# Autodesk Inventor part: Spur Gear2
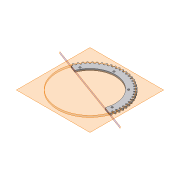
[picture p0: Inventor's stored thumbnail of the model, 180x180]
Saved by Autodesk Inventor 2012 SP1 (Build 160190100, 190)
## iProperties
Created: 2006-09
Part Number: Spur Gear2
Document SubType Name: Modeling
Mass: 24.3665 g
Surface Area: 142.188 cm^2
Volume: 24.3665 cm^3
Density: 1 g/cm^3
Material: Default
CustomPartVersion: 1
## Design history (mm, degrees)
sketch "Sketch1"
  geometry: C1 r 93 at (0, 0)
  constraints: 1 centre point
  dimensions: "d0" = 186 diameter of C1 (= da_da)
extrude "Extrusion1" new body sketch "Sketch1" distance "d1" = 5 (= da_b); taper "d2" = 0 deg
workplane "Work Plane2"
sketch "Sketch2"
  geometry: C1 r 93 at (0, 0) reference; C2 r 90 at (0, 0)
  constraints: 1 centre point, 1 coincident
  dimensions: "d3" = 180 diameter of C2 (= da_dw)
extrude_surface "ExtrusionSrf1" sketch "Sketch2" dims "d4" = 10, "d5" = 0
workplane "Work Plane8"
workplane "Work Plane9"
feature "Spur Gear" dims "da_b" = 5, "da_d" = 180, "da_aw" = 120, "da_da" = 186, "da_df" = 172.5, "da_dw" = 180, angle "da_beta" = 0 deg, "da_lefttooth" = 0, "da_righttooth" = 0
workplane "Work Plane11"
workplane "Work Plane12"
split "Split1"
sketch "Sketch4"
  geometry: L1 (-143.165, 52.108)-(165.406, -60.203) reference; L2 (-65.778, 23.941)-(65.778, -23.941); A1 r 70 centre (0, 0) between (65.778, -23.941) and (-65.778, 23.941); 1 further point
  constraints: 2 end point, 2 point on circle, 1 centre point, 1 coincident, 1 collinear, 1 point on line
  dimensions: "d51" = 70 radius of A1
extrude "Extrusion2" cut sketch "Sketch4" stored distance "d52" = 10; taper "d53" = 0 deg
sketch "Sketch5"
  geometry: 1 further point
hole "Hole1" sketch "Sketch5" at (65.818, 38) diameter "d54" = 5.5; stored, may be unused: countersink angle "d58" = 90 deg, drill point angle "d60" = 0 deg; dims "d55" = 6, "d56" = 4, "d57" = 2, "d59" = 8
sketch "Sketch9"
  geometry: 1 further point
hole "Hole5" sketch "Sketch9" at (8.823, 75.486) diameter "d82" = 5.5; stored, may be unused: countersink angle "d86" = 90 deg, drill point angle "d88" = 0 deg; dims "d83" = 6, "d84" = 4, "d85" = 2, "d87" = 8
sketch "Sketch10"
  geometry: 1 further point
hole "Hole6" sketch "Sketch10" at (-55.28, 52.154) diameter "d89" = 5.5; stored, may be unused: countersink angle "d93" = 90 deg, drill point angle "d95" = 0 deg; dims "d90" = 6, "d91" = 4, "d92" = 2, "d94" = 8
sketch "Sketch11"
  geometry: 1 further point
hole "Hole7" sketch "Sketch11" at (-74.845, -13.197) diameter "d96" = 5.5; stored, may be unused: countersink angle "d100" = 90 deg, drill point angle "d102" = 0 deg; dims "d97" = 6, "d98" = 4, "d99" = 2, "d101" = 8
body "Solid1"
body "Srf1"
other parameters: "d17" = 0, "d34" = 3 deg (computed from da_z), "d39" = 0, "d41" = 0, "d47" = 0, "d48" = 0, "d50" = -20 deg
